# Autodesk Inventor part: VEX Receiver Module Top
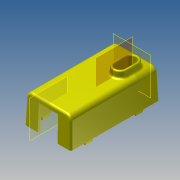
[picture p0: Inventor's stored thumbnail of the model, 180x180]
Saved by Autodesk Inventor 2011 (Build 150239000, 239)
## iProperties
Created: 2010-06
Part Number: VEX Receiver Module Top
Document SubType Name: Modeling
Designer: Phil
Density: 1 g/cm^3
Author: Phil
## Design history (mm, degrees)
sketch "Sketch1"
  geometry: L1 (49.824, 2.041)-(-2.881, 2.041); L2 (-2.881, -25.439)-(49.824, -25.439); L3 (49.824, -25.439)-(49.824, 2.041); L4 (-2.881, -25.439)-(-2.881, 2.041)
  constraints: 8 end point, 1 horizontal, 1 parallel
extrude "Extrusion1" new body sketch "Sketch1" distance "d0" = 17.5006; taper "d1" = -2 deg
sketch "Sketch2"
  geometry: L1 (40.724, -24.759)-(40.724, -24.159); L2 (36.424, -24.959)-(40.524, -24.959); L3 (36.424, -23.959)-(6.424, -23.959); L4 (6.424, 0.541)-(40.524, 0.541); L5 (45.052, -23.959)-(36.424, -23.959); L6 (45.017, -23.819)-(46.23, -23.819); L7 (47.719, -23.819)-(48.185, -23.819); L8 (36.224, -24.759)-(36.224, -24.159); L9 (0.719, -23.819)-(1.932, -23.819); L10 (-1.236, -23.819)-(-0.77, -23.819); L11 (-1.236, -21.817)-(-1.236, -23.819); L12 (48.185, -23.819)-(48.185, -21.817); L13 (6.224, -24.759)-(6.224, -24.159); L14 (6.424, -23.959)-(1.897, -23.959); L15 (6.424, -24.959)-(10.524, -24.959); L16 (10.724, -24.159)-(10.724, -24.759); L17 (10.724, 1.341)-(10.724, 0.741); L18 (10.524, 1.541)-(6.424, 1.541); L19 (-1.236, 0.402)-(-1.236, -1.601); L20 (-0.77, 0.402)-(-1.236, 0.402); L21 (1.932, 0.402)-(0.719, 0.402); L22 (1.897, 0.541)-(6.424, 0.541); L23 (6.224, 0.741)-(6.224, 1.341); L24 (48.185, -1.601)-(48.185, 0.402); L25 (48.185, 0.402)-(47.719, 0.402); L26 (46.23, 0.402)-(45.017, 0.402); L27 (40.524, 0.541)-(45.052, 0.541); L28 (40.724, 1.341)-(40.724, 0.741); L29 (36.224, 0.741)-(36.224, 1.341); L30 (40.524, 1.541)-(36.424, 1.541); L31 (-1.376, -21.933)-(-1.376, -1.484); L32 (48.324, -21.933)-(48.324, -1.484); A1 r 0.85 centre (46.974, -23.409) between (46.23, -23.819) and (47.719, -23.819); A2 r 2 centre (46.974, -23.409) between (45.017, -23.819) and (45.052, -23.959); A3 r 2 centre (-0.026, -23.409) between (1.897, -23.959) and (1.932, -23.819); A4 r 0.85 centre (-0.026, -23.409) between (-0.77, -23.819) and (0.719, -23.819); A5 r 2 centre (-0.026, -23.409) between (-1.236, -21.817) and (-1.376, -21.933); A6 r 2 centre (46.974, -23.409) between (48.324, -21.933) and (48.185, -21.817); A7 r 2 centre (-0.026, -0.009) between (-1.376, -1.484) and (-1.236, -1.601); A8 r 2 centre (-0.026, -0.009) between (1.932, 0.402) and (1.897, 0.541); A9 r 0.85 centre (-0.026, -0.009) between (0.719, 0.402) and (-0.77, 0.402); A10 r 2 centre (46.974, -0.009) between (48.185, -1.601) and (48.324, -1.484); A11 r 2 centre (46.974, -0.009) between (45.052, 0.541) and (45.017, 0.402); A12 r 0.85 centre (46.974, -0.009) between (47.719, 0.402) and (46.23, 0.402); 6 further points
  constraints: 64 end point, 24 point on circle, 12 centre point, 4 point on line, 52 other
extrude "Extrusion2" cut sketch "Sketch2" distance "d2" = 16.002; taper "d3" = 0 deg
extrude "Extrusion3" join sketch "Sketch2" distance "d4" = 1.778; taper "d5" = -2 deg
fillet "Fillet1" dims "d6" = 3.175
fillet "Fillet2" dims "d7" = 1.27
fillet "Fillet3" dims "d8" = 0.127
sketch "Sketch3"
  geometry: L1 (0, 18.35)-(14.848, 18.221); L2 (14.848, 18.221)-(14.848, 6.721); L3 (14.848, 6.721)-(0, 6.591); L4 (16.285, 22.533)-(16.285, 2.408) reference; L5 (0, 24.941)-(0, 0) reference; 3 further points
  constraints: 6 end point, 2 midpoint, 2 point on line, 1 horizontal alignment
extrude "Extrusion4" cut sketch "Sketch3" stored distance "d9" = 4.572; taper "d10" = 0 deg
sketch "Sketch4"
  geometry: L1 (-12.313, -12.895)-(-6.013, -12.895); L2 (-12.313, -21.671)-(-6.013, -21.671); A1 r 4.388 centre (-12.313, -17.283) between (-12.313, -12.895) and (-12.313, -21.671); A2 r 4.388 centre (-6.013, -17.283) between (-6.013, -21.671) and (-6.013, -12.895); 2 further points
  constraints: 4 end point, 4 point on circle, 4 tangent, 2 centre point, 1 horizontal, 1 parallel
  dimensions: "d11" = 6.3 distance of L1.start L1.end
extrude "Extrusion5" join sketch "Sketch4" distance "d12" = 3.937; taper "d13" = -2 deg
fillet "Fillet4" dims "d14" = 1.27
sketch "Sketch5"
  geometry: L1 (-12.313, -13.033)-(-6.013, -13.033) reference; L2 (-6.013, -21.534)-(-12.313, -21.534) reference; L3 (-6.013, -14.386)-(-12.313, -14.386); L4 (-12.313, -20.18)-(-6.013, -20.18); A1 r 4.251 centre (-12.313, -17.283) between (-12.313, -13.033) and (-12.313, -21.534) reference; A2 r 4.251 centre (-6.013, -17.283) between (-6.013, -21.534) and (-6.013, -13.033) reference; A3 r 2.897 centre (-12.313, -17.283) between (-12.313, -14.386) and (-12.313, -20.18); A4 r 2.897 centre (-6.013, -17.283) between (-6.013, -20.18) and (-6.013, -14.386); 1 further point
  constraints: 4 end point, 4 point on circle, 2 centre point, 3 other
extrude "Extrusion7" join sketch "Sketch5" distance "d17" = 10.287; taper "d18" = 0 deg
extrude "Extrusion8" cut sketch "Sketch5" stored distance "d19" = 4.0005; taper "d20" = 0 deg
chamfer "Chamfer1" distance "d21" = 0.508; stored, may be unused: second distance "d22" = 3.175, angle "d23" = 45 deg
fillet "Fillet5" dims "d24" = 0.635
sketch "Sketch6"
  geometry: L1 (0, 0)-(0, 24.941) reference; L2 (0, 8.129)-(-0.696, 8.129); L3 (-0.696, 13.83)-(0, 13.83); A1 r 2.85 centre (-0.696, 10.979) between (-0.696, 13.83) and (-0.696, 8.129); 1 further point
  constraints: 4 end point, 2 point on circle, 2 point on line, 2 tangent, 1 centre point, 1 parallel, 1 perpendicular
  dimensions: "d26" = 0.69566 distance of L2.start L2.end; "d29" = 5.70022 distance between parallel lines of L3 L2
workplane "Work Plane2"
  workplane "Work Plane1"
sketch "Sketch7"
  geometry: L1 (8.129, 0)-(8.129, -0.695) reference; L2 (13.83, -0.695)-(13.83, 0) reference; L3 (12.824, 0)-(12.824, -0.695); L4 (9.135, -0.695)-(9.135, 0); L5 (9.135, 0)-(12.824, 0); 2 further points; 1 other entity
  constraints: 6 end point, 2 parallel, 1 horizontal alignment, 1 perpendicular, 3 other
loft "Loft1" dims "d37" = 0, "d38" = 90 deg, "d39" = 0, "d40" = 90 deg
sketch "Sketch8"
  geometry: L1 (0, 3.689)-(-0.695, 3.689) reference; L2 (0, 0)-(0, 3.689) reference; L3 (-0.695, 3.17)-(-0.519, 3.17); L4 (-0.519, 0.519)-(-0.695, 0.519); L5 (-0.519, 0.519)-(0, 0.519); L6 (-0.519, 3.17)-(0, 3.17); 2 further points
  constraints: 8 end point, 2 perpendicular, 2 point on line, 2 vertical alignment, 1 parallel, 2 other
extrude "Extrusion10" cut sketch "Sketch8" stored distance "d42" = 6.35; taper "d43" = 0 deg
fillet "Fillet9" dims "d44" = 1.27
fillet "Fillet10" dims "d45" = 0.508
fillet "Fillet11" dims "d46" = 0.127
fillet "Fillet12" dims "d47" = 0.508
workplane "Work Plane3"
workplane "Work Plane4"
workplane "Work Plane5"
body "Solid1"
other parameters: "d35" = 0, "d41" = -1.5875
